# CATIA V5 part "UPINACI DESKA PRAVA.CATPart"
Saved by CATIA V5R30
Part number: UPINACI DESKA PRAVA
Bounding box of the stored display mesh (mm): x 0 to 36, y -273 to 273, z -173 to 173
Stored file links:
  C:\Users\ondra\Desktop\PŘÍLOHA P III\CATIA\UPINACI DESKA PRAVA.CATPart
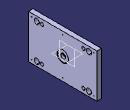
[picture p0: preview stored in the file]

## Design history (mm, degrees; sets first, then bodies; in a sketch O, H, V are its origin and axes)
Set1
  DatumSurface1 to DatumSurface37 "K12/346x"
  Plane1: type Offset, RefPlane yz-plane, Offset 36
  Plane2: type Offset, RefPlane yz-plane, Offset 32
  Plane3: type Offset, RefPlane yz-plane, Offset 36
  Join1: Elements (DatumSurface1; DatumSurface2; DatumSurface3; DatumSurface4; DatumSurface5; DatumSurface6; DatumSurface7; DatumSurface8; DatumSurface9; DatumSurface10; DatumSurface11; DatumSurface12; DatumSurface13; DatumSurface14; DatumSurface15; DatumSurface16; DatumSurface17; DatumSurface18; DatumSurface19; DatumSurface20; DatumSurface21; DatumSurface22; DatumSurface23; DatumSurface24; DatumSurface25; DatumSurface26; DatumSurface27; DatumSurface28; DatumSurface29; DatumSurface30; DatumSurface31; DatumSurface32; DatumSurface33; DatumSurface34; DatumSurface35; DatumSurface36; DatumSurface37)
Body1 (main body)
  DatumPoint1
  CloseSurface1: CloseElement Join1
  Sketch1 on {plane type Tangent, Support face of CloseSurface1, RefPoint vertex of DatumPoint1}, origin (-280, -248, -148), H (0, 1, 0), V (0, 0, -1)
    point P1 (0, 0)
    reference projected point E1 (0, 0) from vertex of DatumPoint1
    coincidence: E1 P1
  Hole1: placed by Sketch1, at (36, -248, -148) direction (-1, 0, 0), diameter 4.917, depth 8, V-bottom angle 120, threaded "M6", thread diameter 6, thread depth 7, pitch 1
  Sketch2, origin (-280, 0, 0), H (0, 1, 0), V (0, 0, -1), geometry linked from another document
  UserPattern1: of Hole1, copies 6, at the points of Sketch2
  DatumPoint2
  Plane4: type Offset, RefPlane yz-plane, Offset 15
  Sketch3 on {plane type Tangent, Support face of CloseSurface1, RefPoint vertex of DatumPoint2}, origin (-288.5, -39, 0), H (0, 1, 0), V (0, 0, -1)
    point P1 (0, 0)
    reference projected point E1 (0, 0) from vertex of DatumPoint2
    coincidence: E1 P1
  Hole2: placed by Sketch3, at (32, -39, 0) direction (-1, 0, 0), diameter 4.134, depth 15, V-bottom angle 120, threaded "M5", thread diameter 5, thread depth 13, pitch 0.8
  Sketch4, origin (-288.5, 0, 0), H (0, 0, 1), V (0, 1, 0), geometry linked from another document
  UserPattern2: of Hole2, copies 3, at the points of Sketch4
  Point1: type OnSurface, Support face of CloseSurface1, Length 0, Direction (0, -0.216, 0.9764)
  Sketch5 on {plane type Tangent, Support face of CloseSurface1, RefPoint Point1}, origin (32, 0, 0), H (0, 1, 0), V (0, 0, -1)
    point P1 (0, 0)
    reference projected point E1 (0, 0) from Point1
    coincidence: E1 P1
  Hole3: placed by Sketch5, at (32, 0, 0) direction (-1, 0, 0), diameter 18, through (limit type 6), counterbore diameter 38, counterbore depth 18
  Fillet1: radius 3, on edge [face of Hole3 | face of Hole3]
  Chamfer1: length 0.5, angle 45, on edge [face of Hole3 | face of Hole3]
  Plane5: stored without definition
  Point2: type OnPlane, Support Plane5, H 15, V 0, Direction (0, 1, 0)
  Sketch6 on face of Hole3, origin (14, 15, 0), H (0, 1, 0), V (0, 0, 1)
    point P1 (0, 0)
    reference projected point E1 (0, 0) from Point2
    coincidence: E1 P1
  Hole4: placed by Sketch6, at (14, 15, 0) direction (-1, 0, 0), diameter 4, depth 6, V-bottom angle 120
